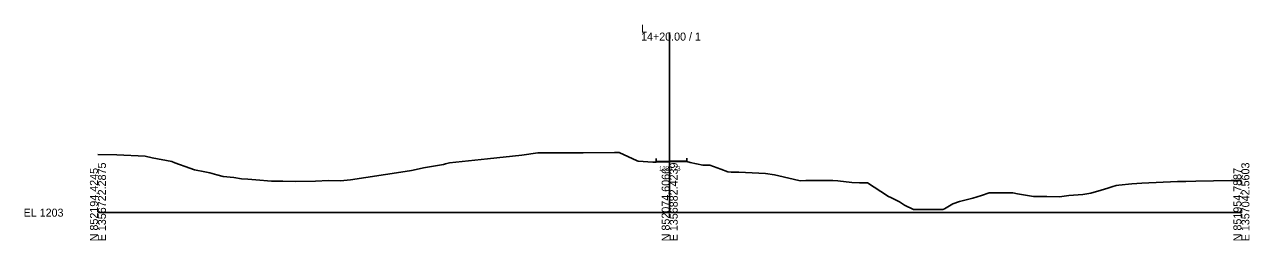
# Model space of a CAD drawing. Extents: x -26 to 3203, y -10 to 4066.
# Drawn here: x -25.7 to 402.8, y 3990.3 to 4065.6 of the extents above; entities that cross this region are included whole.
import ezdxf

# ---------------------------------------------------------------- set-up
doc = ezdxf.new("R2010")
doc.units = 0
for name, color, linetype in [('Exist Cross Section Cell', 7, 'Continuous'), ('Exist XS Center Line Elevation Label', 7, 'Continuous'), ('Exist XS Ground Line', 7, 'Continuous'), ('Prop XS Dump Level', 7, 'Continuous'), ('Prop XS EOT Tick Mark', 7, 'Continuous'), ('Prop XS Finish Grade Earthwork', 7, 'Continuous'), ('Prop XS Finish Grade Pavement', 7, 'Continuous')]:
    doc.layers.add(name, color=color, linetype=linetype)

msp = doc.modelspace()

# ---------------------------------------------------------------- linework, layer by layer
at = {"layer": 'Exist Cross Section Cell'}
for p, q in [((200, 4000), (200, 4062.83)), ((0, 4000), (200, 4000)), ((200, 4000), (400, 4000))]:
    msp.add_line(p, q, dxfattribs=at)
at = {"layer": 'Exist XS Ground Line'}
for p, q in [((0, 4020.32), (6.57, 4020.13)), ((6.57, 4020.13), (16.48, 4019.69)), ((16.48, 4019.69), (18.93, 4019.16)), ((136.24, 4018.79), (148.25, 4020.04)), ((148.25, 4020.04), (153.93, 4020.89)), ((153.93, 4020.89), (169.79, 4020.89)), ((169.79, 4020.89), (180.67, 4020.94)), ((180.67, 4020.94), (182.29, 4020.94)), ((182.29, 4020.94), (188.62, 4018.11)), ((18.93, 4019.16), (25.87, 4017.82)), ((25.87, 4017.82), (26.87, 4017.43)), ((26.87, 4017.43), (32.12, 4015.53)), ((32.12, 4015.53), (33.78, 4014.95)), ((109.69, 4014.69), (113.47, 4015.58)), ((113.47, 4015.58), (113.88, 4015.63)), ((113.88, 4015.63), (120.88, 4016.85)), ((120.88, 4016.85), (121.55, 4017.09)), ((121.55, 4017.09), (123.02, 4017.34)), ((123.02, 4017.34), (136.24, 4018.79)), ((188.62, 4018.11), (188.93, 4017.95)), ((188.93, 4017.95), (194.17, 4017.67)), ((194.17, 4017.67), (195.27, 4017.65)), ((195.27, 4017.65), (200, 4017.73)), ((200, 4017.73), (204.66, 4017.81)), ((204.66, 4017.81), (205.96, 4017.81)), ((205.96, 4017.81), (207.23, 4017.54)), ((207.23, 4017.54), (211.6, 4016.52)), ((211.6, 4016.52), (214, 4016.56)), ((214, 4016.56), (217.88, 4015.2)), ((33.78, 4014.95), (37.44, 4014.29)), ((37.44, 4014.29), (39.18, 4013.84)), ((39.18, 4013.84), (41.6, 4013.24)), ((41.6, 4013.24), (43.8, 4012.67)), ((43.8, 4012.67), (47.53, 4012.24)), ((47.53, 4012.24), (50.25, 4011.78)), ((50.25, 4011.78), (52.4, 4011.7)), ((52.4, 4011.7), (55.27, 4011.44)), ((55.27, 4011.44), (60.68, 4010.97)), ((76.1, 4011.01), (80.67, 4011.17)), ((80.67, 4011.17), (84.9, 4011.14)), ((84.9, 4011.14), (88.35, 4011.41)), ((88.35, 4011.41), (105.91, 4014.08)), ((105.91, 4014.08), (109.69, 4014.69)), ((217.88, 4015.2), (220.3, 4014.25)), ((220.3, 4014.25), (221.56, 4014.17)), ((221.56, 4014.17), (224.22, 4014.11)), ((224.22, 4014.11), (231.21, 4013.82)), ((231.21, 4013.82), (233.48, 4013.64)), ((233.48, 4013.64), (236.68, 4013.24)), ((236.68, 4013.24), (243.24, 4011.68)), ((243.24, 4011.68), (245.67, 4011.13)), ((245.67, 4011.13), (247.58, 4011.23)), ((247.58, 4011.23), (248.18, 4011.26)), ((248.18, 4011.26), (249.38, 4011.26)), ((249.38, 4011.26), (257.11, 4011.23)), ((257.11, 4011.23), (258.79, 4011.12)), ((258.79, 4011.12), (263.68, 4010.52)), ((384.01, 4011.02), (396.42, 4011.22)), ((396.42, 4011.22), (400, 4011.22)), ((60.68, 4010.97), (64.62, 4011.03)), ((64.62, 4011.03), (69.16, 4010.85)), ((69.16, 4010.85), (76.1, 4011.01)), ((263.68, 4010.52), (266.41, 4010.41)), ((266.41, 4010.41), (269.23, 4010.38)), ((269.23, 4010.38), (273.86, 4007.44)), ((273.86, 4007.44), (276.54, 4005.59)), ((309.07, 4006), (311.76, 4006.96)), ((311.76, 4006.96), (320.08, 4006.87)), ((320.08, 4006.87), (321.71, 4006.6)), ((344.53, 4006.3), (347.28, 4006.82)), ((347.28, 4006.82), (350.91, 4007.9)), ((350.91, 4007.9), (353.25, 4008.56)), ((353.25, 4008.56), (354.66, 4008.99)), ((354.66, 4008.99), (356.24, 4009.44)), ((356.24, 4009.44), (357.13, 4009.55)), ((357.13, 4009.55), (361.63, 4010.11)), ((361.63, 4010.11), (365.18, 4010.26)), ((365.18, 4010.26), (377.69, 4010.82)), ((377.69, 4010.82), (380.53, 4010.91)), ((380.53, 4010.91), (384.01, 4011.02)), ((276.54, 4005.59), (277.35, 4005.34)), ((277.35, 4005.34), (280.4, 4003.82)), ((280.4, 4003.82), (282.17, 4002.67)), ((282.17, 4002.67), (285.33, 4001.08)), ((296.1, 4001.36), (299.06, 4003.1)), ((299.06, 4003.1), (301.4, 4003.87)), ((301.4, 4003.87), (306.07, 4005.03)), ((306.07, 4005.03), (309.07, 4006)), ((321.71, 4006.6), (327.23, 4005.61)), ((327.23, 4005.61), (331.93, 4005.61)), ((331.93, 4005.61), (336.42, 4005.48)), ((336.42, 4005.48), (339.66, 4005.97)), ((339.66, 4005.97), (344.53, 4006.3)), ((285.33, 4001.08), (287.64, 4001.08)), ((287.64, 4001.08), (292.22, 4001.08)), ((292.22, 4001.08), (295.59, 4001.08)), ((295.59, 4001.08), (296.1, 4001.36))]:
    msp.add_line(p, q, dxfattribs=at)
at = {"layer": 'Prop XS Dump Level'}
for p, q in [((195.31, 4017.85), (200, 4017.94)), ((200, 4017.94), (206, 4018.06))]:
    msp.add_line(p, q, dxfattribs=at)
at = {"layer": 'Prop XS EOT Tick Mark'}
for p, q in [((195.31, 4017.85), (195.31, 4018.85)), ((206, 4018.06), (206, 4019.06))]:
    msp.add_line(p, q, dxfattribs=at)
at = {"layer": 'Prop XS Finish Grade Earthwork'}
msp.add_line((206, 4018.06), (206, 4017.8), dxfattribs=at)
at = {"layer": 'Prop XS Finish Grade Pavement'}
for p, q in [((195.31, 4017.85), (200, 4017.94)), ((200, 4017.94), (206, 4018.06))]:
    msp.add_line(p, q, dxfattribs=at)

# ---------------------------------------------------------------- texts
at = {"layer": 'Exist Cross Section Cell'}
for s, p in [('14+20.00 / 1', (190, 4060.03)), ('L', (190, 4062.83)), ('EL 1203', (-26, 3998.6))]:
    msp.add_text(s, height=2.8, dxfattribs=at).set_placement(p)
for s, p in [('N 852194.4245', (0, 3990)), ('E 1356722.2875', (2.8, 3990)), ('N 852074.6066', (200, 3990)), ('E 1356882.4239', (202.8, 3990)), ('N 851954.7887', (400, 3990)), ('E 1357042.5603', (402.8, 3990))]:
    msp.add_text(s, height=2.8, rotation=90, dxfattribs=at).set_placement(p)
at = {"layer": 'Exist XS Center Line Elevation Label'}
msp.add_text('1220.73', height=1.5, dxfattribs=at).set_placement((196.31, 4014.68))

doc.saveas('drawing.dxf')
